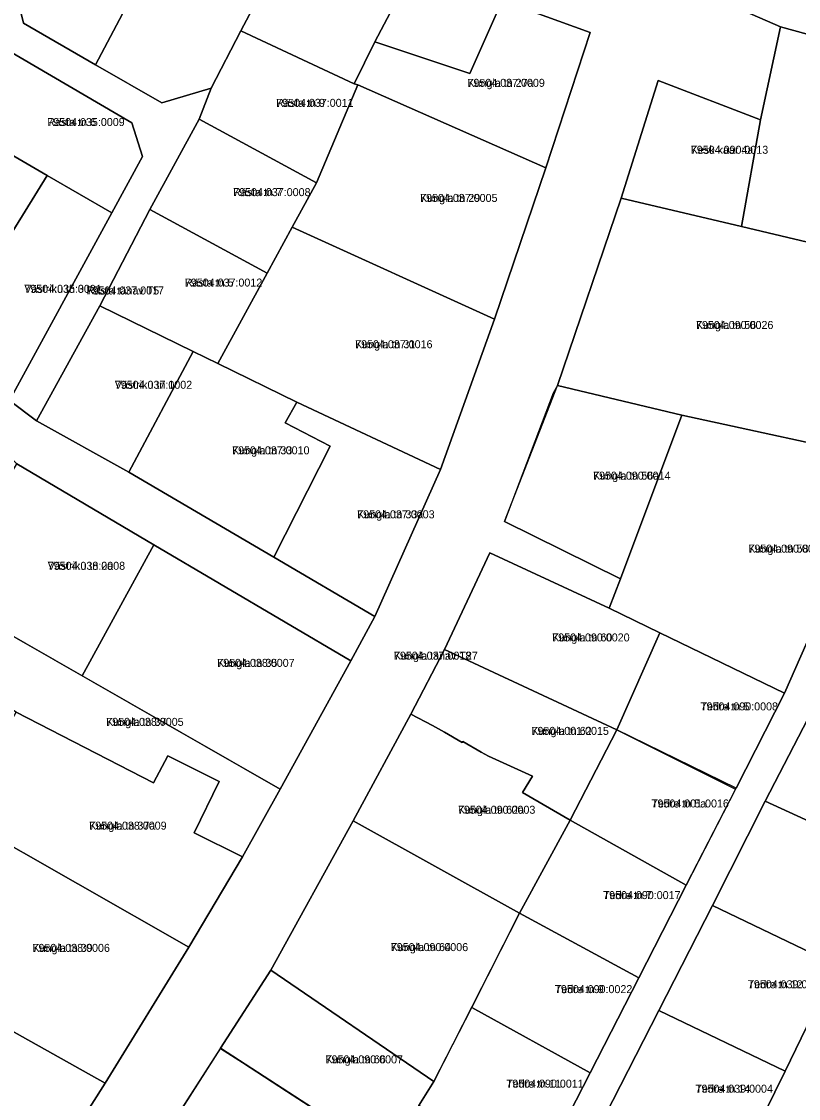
# Model space of a CAD drawing. Extents: x 643847 to 663718, y 6468443 to 6482775.
# Drawn here: x 658655.7 to 658801.3, y 6471870.9 to 6472072.8 of the extents above; entities that cross this region are included whole.
import ezdxf

# ---------------------------------------------------------------- set-up
doc = ezdxf.new("R2010")
doc.units = 0
for name, color, linetype in [('L_AADRESS', 7, 'Continuous'), ('PIIR', 7, 'Continuous'), ('TUNNUS', 7, 'Continuous')]:
    doc.layers.add(name, color=color, linetype=linetype)

msp = doc.modelspace()

# ---------------------------------------------------------------- linework, layer by layer
at = {"layer": 'PIIR'}
for points in [[(658832.21, 6472062.37), (658797.91, 6472071.79), (658752.56, 6472091.57), (658737.66, 6472098.99), (658716.99, 6472109.8), (658699.19, 6472119.89), (658684.01, 6472128.39), (658679.82, 6472130.67), (658655.71, 6472145.26), (658629.38, 6472163.16), (658620.68, 6472168.8), (658610.02, 6472177.32), (658590.68, 6472192.79), (658566.41, 6472214.54), (658542.42, 6472237.59), (658521.37, 6472260.27)], [(658752.56, 6472091.57), (658797.91, 6472071.79), (658794.14, 6472054.38), (658775, 6472061.72), (658768.06, 6472039.68), (658756.09, 6472004.53), (658755.31, 6472003.13), (658746.16, 6471979.05), (658767.91, 6471968.32), (658765.78, 6471962.8), (658743.42, 6471973.14), (658734.96, 6471955.06), (658728.64, 6471942.91), (658717.81, 6471922.95), (658702.38, 6471894.92), (658692.98, 6471880.27), (658684.33, 6471866.81)], [(658653.01, 6471844.82), (658671.36, 6471873.72), (658687.03, 6471899.24), (658697.08, 6471916.15), (658704.12, 6471928.88), (658717.4, 6471952.9), (658721.88, 6471961.21), (658734.18, 6471988.79), (658744.29, 6472016.99), (658753.94, 6472045.33), (658762.23, 6472070.73), (658748.23, 6472075.76)], [(658753.11, 6471857.85), (658762.22, 6471875.65), (658771.33, 6471893.46), (658780.25, 6471910.88), (658789.57, 6471929.06), (658798.67, 6471946.86), (658817.98, 6471990.6)], [(658811.09, 6471957.62), (658795.05, 6471926.61), (658785.16, 6471907.04), (658775.09, 6471887.37), (658765.02, 6471867.7)]]:
    msp.add_lwpolyline(points, dxfattribs=at)
for points in [[(658670.36, 6472019.49), (658658.46, 6471997.89), (658653.44, 6472001.73), (658672.58, 6472036.92), (658678.34, 6472047.5), (658676.34, 6472053.77), (658649.48, 6472069.46), (658644.52, 6472072.15), (658648.05, 6472077.18), (658658.22, 6472094.28), (658668.68, 6472111.88), (658679.82, 6472130.67), (658684.01, 6472128.39), (658667.09, 6472099.2), (658654.75, 6472077.92), (658656.02, 6472072.5), (658669.53, 6472064.64), (658681.97, 6472057.51), (658691.21, 6472060.31), (658688.96, 6472054.5), (658679.74, 6472037.54)], [(658737.66, 6472098.99), (658721.87, 6472068.98), (658718.03, 6472061.11), (658696.76, 6472071.01), (658701.56, 6472080.14), (658716.99, 6472109.8)], [(658667.09, 6472099.2), (658683.12, 6472090.34), (658669.53, 6472064.64), (658656.02, 6472072.5), (658654.75, 6472077.92)], [(658752.56, 6472091.57), (658748.23, 6472075.76), (658744.7, 6472074.32), (658739.68, 6472063.05), (658721.87, 6472068.98), (658737.66, 6472098.99)], [(658683.12, 6472090.34), (658701.56, 6472080.14), (658696.76, 6472071.01), (658691.21, 6472060.31), (658681.97, 6472057.51), (658669.53, 6472064.64)], [(658753.94, 6472045.33), (658718.7, 6472060.93), (658718.03, 6472061.11), (658721.87, 6472068.98), (658739.68, 6472063.05), (658744.7, 6472074.32), (658748.23, 6472075.76), (658762.23, 6472070.73)], [(658691.21, 6472060.31), (658696.76, 6472071.01), (658718.03, 6472061.11), (658718.7, 6472060.93), (658710.92, 6472042.56), (658688.96, 6472054.5)], [(658797.91, 6472071.79), (658832.21, 6472062.37), (658826.08, 6472030.85), (658825.24, 6472026.13), (658806.64, 6472030.54), (658790.59, 6472034.34), (658794.14, 6472054.38)], [(658660.46, 6472043.93), (658640.91, 6472055.26), (658643.98, 6472060.39), (658649.48, 6472069.46), (658676.34, 6472053.77), (658678.34, 6472047.5), (658672.58, 6472036.92)], [(658702.98, 6471972.36), (658721.88, 6471961.21), (658717.4, 6471952.9), (658680.49, 6471974.69), (658654.8, 6471989.86), (658643.37, 6472000.79), (658627.34, 6472010.99), (658601.6, 6472028.15), (658576.22, 6472045.38), (658551.14, 6472062.72), (658555.3, 6472067.81), (658572.96, 6472054.74), (658589.6, 6472043.55), (658604.12, 6472033.8), (658621.01, 6472022.68), (658639.83, 6472010.5), (658653.44, 6472001.73), (658658.46, 6471997.89), (658675.78, 6471988.27)], [(658744.29, 6472016.99), (658706.41, 6472034.26), (658710.92, 6472042.56), (658718.7, 6472060.93), (658753.94, 6472045.33)], [(658768.06, 6472039.68), (658775, 6472061.72), (658794.14, 6472054.38), (658790.59, 6472034.34)], [(658621.01, 6472022.68), (658640.91, 6472055.26), (658660.46, 6472043.93), (658639.83, 6472010.5)], [(658701.7, 6472025.6), (658679.74, 6472037.54), (658688.96, 6472054.5), (658710.92, 6472042.56), (658706.41, 6472034.26)], [(658639.83, 6472010.5), (658660.46, 6472043.93), (658672.58, 6472036.92), (658653.44, 6472001.73)], [(658756.09, 6472004.53), (658768.06, 6472039.68), (658790.59, 6472034.34), (658806.64, 6472030.54), (658805.88, 6472025.25), (658803.75, 6472010.3), (658824.04, 6472005.4), (658817.98, 6471990.6), (658779.42, 6471998.97)], [(658679.74, 6472037.54), (658701.7, 6472025.6), (658692.48, 6472008.64), (658687.84, 6472010.92), (658670.36, 6472019.49)], [(658744.29, 6472016.99), (658734.18, 6471988.79), (658707.27, 6472001.43), (658692.48, 6472008.64), (658701.7, 6472025.6), (658706.41, 6472034.26)], [(658658.46, 6471997.89), (658670.36, 6472019.49), (658687.84, 6472010.92), (658675.78, 6471988.27)], [(658702.98, 6471972.36), (658675.78, 6471988.27), (658687.84, 6472010.92), (658692.48, 6472008.64), (658707.27, 6472001.43), (658705.1, 6471997.57), (658713.5, 6471993.2)], [(658746.16, 6471979.05), (658756.09, 6472004.53), (658779.42, 6471998.97), (658767.91, 6471968.32)], [(658721.88, 6471961.21), (658702.98, 6471972.36), (658713.5, 6471993.2), (658705.1, 6471997.57), (658707.27, 6472001.43), (658734.18, 6471988.79)], [(658765.78, 6471962.8), (658767.91, 6471968.32), (658779.42, 6471998.97), (658817.98, 6471990.6), (658798.67, 6471946.86), (658775.32, 6471958.2)], [(658680.49, 6471974.69), (658667.01, 6471950.13), (658640.51, 6471965.31), (658654.8, 6471989.86)], [(658704.12, 6471928.88), (658667.01, 6471950.13), (658680.49, 6471974.69), (658717.4, 6471952.9)], [(658743.42, 6471973.14), (658765.78, 6471962.8), (658775.32, 6471958.2), (658767.22, 6471939.98), (658734.96, 6471955.06)], [(658697.08, 6471916.15), (658688.03, 6471920.65), (658692.74, 6471930.28), (658683.07, 6471935.09), (658680.4, 6471930.02), (658654.69, 6471943.3), (658635.14, 6471956.08), (658640.51, 6471965.31), (658704.12, 6471928.88)], [(658789.57, 6471929.06), (658767.22, 6471939.98), (658775.32, 6471958.2), (658798.67, 6471946.86)], [(658811.09, 6471957.62), (658833.33, 6471948.59), (658838.88, 6471946.33), (658830.92, 6471929.72), (658823.11, 6471913.42), (658818.32, 6471915.91), (658795.05, 6471926.61)], [(658734.96, 6471955.06), (658767.22, 6471939.98), (658758.51, 6471923.03), (658749.58, 6471928.22), (658751.4, 6471931.3), (658743.16, 6471935.03), (658741.81, 6471935.81), (658738.35, 6471937.81), (658738.24, 6471937.62), (658734.92, 6471939.52), (658732.68, 6471940.79), (658728.64, 6471942.91)], [(658697.08, 6471916.15), (658687.03, 6471899.24), (658645.38, 6471922.99), (658643.83, 6471923.88), (658654.69, 6471943.3), (658680.4, 6471930.02), (658683.07, 6471935.09), (658692.74, 6471930.28), (658688.03, 6471920.65)], [(658728.64, 6471942.91), (658732.68, 6471940.79), (658734.92, 6471939.52), (658738.24, 6471937.62), (658738.35, 6471937.81), (658741.81, 6471935.81), (658743.16, 6471935.03), (658751.4, 6471931.3), (658749.58, 6471928.22), (658758.51, 6471923.03), (658749, 6471905.59), (658717.81, 6471922.95)], [(658767.22, 6471939.98), (658789.48, 6471928.86), (658780.25, 6471910.88), (658758.51, 6471923.03)], [(658795.05, 6471926.61), (658818.32, 6471915.91), (658808.48, 6471895.85), (658785.16, 6471907.04)], [(658671.36, 6471873.72), (658630.5, 6471896.61), (658628.72, 6471897.98), (658645.38, 6471922.99), (658687.03, 6471899.24)], [(658717.81, 6471922.95), (658749, 6471905.59), (658732.95, 6471874.05), (658702.38, 6471894.92)], [(658758.51, 6471923.03), (658780.25, 6471910.88), (658771.33, 6471893.46), (658749, 6471905.59)], [(658785.16, 6471907.04), (658808.48, 6471895.85), (658803.79, 6471886.28), (658798.75, 6471876.01), (658775.09, 6471887.37)], [(658749, 6471905.59), (658771.33, 6471893.46), (658762.22, 6471875.65), (658740.03, 6471887.95)], [(658604.71, 6471871.46), (658622.13, 6471901.72), (658628.72, 6471897.98), (658630.5, 6471896.61), (658671.36, 6471873.72), (658653.01, 6471844.82)], [(658702.38, 6471894.92), (658732.95, 6471874.05), (658730.15, 6471869.54), (658724.23, 6471859.97), (658692.98, 6471880.27)], [(658732.95, 6471874.05), (658740.03, 6471887.95), (658762.22, 6471875.65), (658753.11, 6471857.85), (658730.15, 6471869.54)], [(658775.09, 6471887.37), (658798.75, 6471876.01), (658789.2, 6471856.52), (658765.02, 6471867.7)], [(658836.08, 6471829.38), (658824.52, 6471835.88), (658798.38, 6471850.58), (658789.2, 6471856.52), (658798.75, 6471876.01), (658803.79, 6471886.28), (658853.83, 6471859.94)], [(658692.97, 6471880.26), (658697.07, 6471877.6), (658705.34, 6471872.22), (658724.23, 6471859.97), (658719.91, 6471853.24), (658715.4, 6471846.58), (658714.58, 6471845.3), (658683.51, 6471865.53)]]:
    msp.add_lwpolyline(points, close=True, dxfattribs=at)

# ---------------------------------------------------------------- texts
at = {"layer": 'L_AADRESS'}
for s, p in [('Kungla tn 27a', (658739.24, 6472060.54)), ('Rästa tn 9', (658703.39, 6472056.79)), ('Rästa tn 6', (658660.5, 6472053.19)), ('Kesk kaar 4a', (658781.1, 6472047.99)), ('Rästa tn 7', (658695.33, 6472040.05)), ('Kungla tn 29', (658730.37, 6472038.96)), ('Rästa tn 5', (658686.28, 6472023.09)), ('Västriku tn 3', (658656.2, 6472021.92)), ('Rästa tänav T5', (658667.87, 6472021.61)), ('Kungla tn 56', (658782.07, 6472015.14)), ('Kungla tn 31', (658718.19, 6472011.53)), ('Västriku tn 1', (658673.15, 6472003.93)), ('Kungla tn 33', (658695.14, 6471991.64)), ('Kungla tn 56a', (658762.79, 6471986.89)), ('Kungla tn 33a', (658718.58, 6471979.64)), ('Kungla tn 58', (658791.88, 6471973.21)), ('Västriku tn 2a', (658660.58, 6471969.99)), ('Kungla tn 60', (658755.13, 6471956.56)), ('Kungla tn 35', (658692.35, 6471951.79)), ('Kungla tänav T27', (658725.46, 6471953.14)), ('Tedre tn 5', (658782.93, 6471943.63)), ('Kungla tn 37', (658671.55, 6471940.73)), ('Kungla tn 62', (658751.24, 6471939.04)), ('Tedre tn 5a', (658773.73, 6471925.43)), ('Kungla tn 62a', (658737.46, 6471924.25)), ('Kungla tn 37a', (658668.36, 6471921.27)), ('Tedre tn 7', (658764.67, 6471908.25)), ('Kungla tn 39', (658657.73, 6471898.35)), ('Kungla tn 64', (658724.87, 6471898.5)), ('Tedre tn 12', (658791.79, 6471891.53)), ('Tedre tn 9', (658755.63, 6471890.62)), ('Kungla tn 66', (658712.65, 6471877.45)), ('Tedre tn 11', (658746.52, 6471872.9)), ('Tedre tn 14', (658781.98, 6471871.95))]:
    msp.add_text(s, height=1.5, dxfattribs=at).set_placement(p)
at = {"layer": 'TUNNUS'}
for s, p in [('79504:037:0009', (658739.24, 6472060.54)), ('79504:037:0011', (658703.39, 6472056.79)), ('79504:035:0009', (658660.5, 6472053.19)), ('79504:090:0013', (658781.1, 6472047.99)), ('79504:037:0008', (658695.33, 6472040.05)), ('79504:037:0005', (658730.37, 6472038.96)), ('79504:037:0012', (658686.28, 6472023.09)), ('79504:035:0001', (658656.2, 6472021.92)), ('79504:037:0017', (658667.87, 6472021.61)), ('79504:090:0026', (658782.07, 6472015.14)), ('79504:037:0016', (658718.19, 6472011.53)), ('79504:037:0002', (658673.15, 6472003.93)), ('79504:037:0010', (658695.14, 6471991.64)), ('79504:090:0014', (658762.79, 6471986.89)), ('79504:037:0003', (658718.58, 6471979.64)), ('79504:090:0018', (658791.88, 6471973.21)), ('79504:038:0008', (658660.58, 6471969.99)), ('79504:090:0020', (658755.13, 6471956.56)), ('79504:038:0007', (658692.35, 6471951.79)), ('79504:037:0018', (658725.46, 6471953.14)), ('79504:090:0008', (658782.93, 6471943.63)), ('79504:038:0005', (658671.55, 6471940.73)), ('79504:001:0015', (658751.24, 6471939.04)), ('79504:001:0016', (658773.73, 6471925.43)), ('79504:090:0003', (658737.46, 6471924.25)), ('79504:038:0009', (658668.36, 6471921.27)), ('79504:090:0017', (658764.67, 6471908.25)), ('79504:038:0006', (658657.73, 6471898.35)), ('79504:090:0006', (658724.87, 6471898.5)), ('79504:039:0006', (658791.79, 6471891.53)), ('79504:090:0022', (658755.63, 6471890.62)), ('79504:090:0007', (658712.65, 6471877.45)), ('79504:090:0011', (658746.52, 6471872.9)), ('79504:039:0004', (658781.98, 6471871.95))]:
    msp.add_text(s, height=1.5, dxfattribs=at).set_placement(p)

doc.saveas('drawing.dxf')
